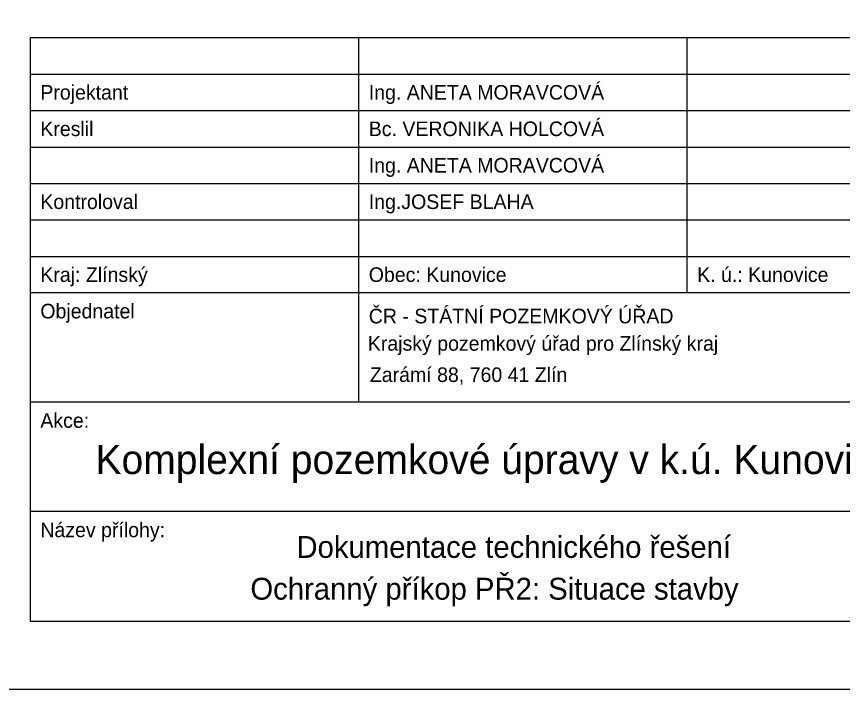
# Model space of a CAD drawing. Extents: x -574342 to -508101, y -1143544 to -1123894.
# Drawn here: x -508312.9 to -508199.7, y -1143536.1 to -1143443.8 of the extents above; entities that cross this region are included whole.
import ezdxf

# ---------------------------------------------------------------- set-up
doc = ezdxf.new("R2010")
doc.units = 0
for name, color, linetype in [('Level 1', 7, 'Continuous'), ('Level 255', 7, 'Continuous'), ('rozpiska', 7, 'Continuous')]:
    doc.layers.add(name, color=color, linetype=linetype)

msp = doc.modelspace()

# ---------------------------------------------------------------- linework, layer by layer
at = {"layer": 'Level 1'}
msp.add_lwpolyline([(-508703.1, -1143116.06), (-508109.1, -1143116.06), (-508109.1, -1143536.06), (-508703.1, -1143536.06)], close=True, dxfattribs=at)
at = {"layer": 'Level 255'}
msp.add_line((-508310.93, -1143526.67), (-508120.96, -1143526.67), dxfattribs=at)
msp.add_line((-508310.93, -1143526.67), (-508120.96, -1143526.67), dxfattribs=at)
msp.add_line((-508310.93, -1143526.67), (-508120.96, -1143526.67), dxfattribs=at)
msp.add_line((-508310.93, -1143526.67), (-508120.96, -1143526.67), dxfattribs=at)
at = {"layer": 'rozpiska'}
for p, q in [((-508310.96, -1143446.67), (-508310.96, -1143526.67)), ((-508310.96, -1143446.67), (-508120.96, -1143446.67)), ((-508265.96, -1143496.67), (-508265.96, -1143446.67)), ((-508220.96, -1143481.67), (-508220.96, -1143446.67)), ((-508310.96, -1143451.67), (-508175.96, -1143451.67)), ((-508310.96, -1143456.67), (-508175.96, -1143456.67)), ((-508310.96, -1143461.67), (-508175.96, -1143461.67)), ((-508310.96, -1143466.67), (-508175.96, -1143466.67)), ((-508310.96, -1143471.67), (-508175.96, -1143471.67)), ((-508310.96, -1143476.67), (-508120.96, -1143476.67)), ((-508120.96, -1143481.67), (-508310.96, -1143481.67)), ((-508120.96, -1143496.67), (-508310.96, -1143496.67)), ((-508120.96, -1143511.67), (-508310.96, -1143511.67)), ((-508310.96, -1143526.67), (-508120.96, -1143526.67)), ((-508310.96, -1143526.67), (-508120.96, -1143526.67))]:
    msp.add_line(p, q, dxfattribs=at)

# ---------------------------------------------------------------- texts
for s, height, p in [('Projektant', 2, (-508309.59, -1143455.17)), ('Ing. ANETA MORAVCOVÁ', 2, (-508264.59, -1143455.17)), ('Bc. VERONIKA HOLCOVÁ', 2, (-508264.59, -1143460.17)), ('Kreslil', 2, (-508309.59, -1143460.17)), ('Ing. ANETA MORAVCOVÁ', 2, (-508264.59, -1143465.17)), ('Kontroloval', 2, (-508309.59, -1143470.17)), ('Ing.JOSEF BLAHA', 2, (-508264.59, -1143470.17)), ('Kraj: Zlínský', 2, (-508309.59, -1143480.17)), ('Obec: Kunovice', 2, (-508264.59, -1143480.17)), ('K. ú.: Kunovice', 2, (-508219.59, -1143480.17)), ('Objednatel', 2, (-508309.59, -1143485.17)), ('ČR - STÁTNÍ POZEMKOVÝ ÚŘAD', 2, (-508264.59, -1143485.85)), ('Krajský pozemkový úřad pro Zlínský kraj ', 2, (-508264.72, -1143489.6)), ('Zarámí 88, 760 41 Zlín', 2, (-508264.44, -1143493.89)), ('Akce:', 2, (-508309.59, -1143500.17)), ('Komplexní pozemkové úpravy v k.ú. Kunovice', 4, (-508302.03, -1143506.52)), ('Název přílohy:', 2, (-508309.59, -1143515.17)), ('Dokumentace technického řešení', 3, (-508274.5, -1143518.01)), ('Ochranný příkop PŘ2: Situace stavby', 3, (-508280.81, -1143523.74))]:
    msp.add_text(s, height=height, dxfattribs=at).set_placement(p)

doc.saveas('drawing.dxf')
